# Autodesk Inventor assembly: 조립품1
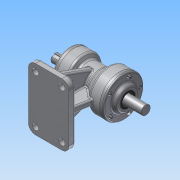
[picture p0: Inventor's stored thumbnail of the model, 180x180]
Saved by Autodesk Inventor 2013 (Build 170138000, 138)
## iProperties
Created: 2015-08
Part Number: 조립품1
Document SubType Name: Assembly
Designer: User11
Author: User11
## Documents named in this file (10)
- C:\Users\User11\Desktop\450805V1018zip\조립품1.iam
- C:\Users\User11\Desktop\450805V1018zip\본체.ipt
- C:\Users\User11\Desktop\450805V1018zip\450805V1018 (2)\M4x0.5.ipt
- C:\Users\User11\Desktop\450805V1018zip\450805V1018 (2)\뒤커버.ipt
- C:\Users\User11\Desktop\450805V1018zip\450805V1018 (2)\베어링 6203.ipt
- C:\Users\User11\Desktop\450805V1018zip\450805V1018 (2)\베어링 6205.ipt
- C:\Users\User11\Desktop\450805V1018zip\450805V1018 (2)\앞커버.ipt
- C:\Users\User11\Desktop\450805V1018zip\450805V1018 (2)\오일실 .ipt
- 오일실 .ipt
- C:\Users\User11\Desktop\450805V1018zip\450805V1018 (2)\축.ipt
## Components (5 placed, 1 different names)
1. M4x0.5:1
2. M4x0.5:2
3. M4x0.5:3
4. M4x0.5:4
5. M4x0.5:5
